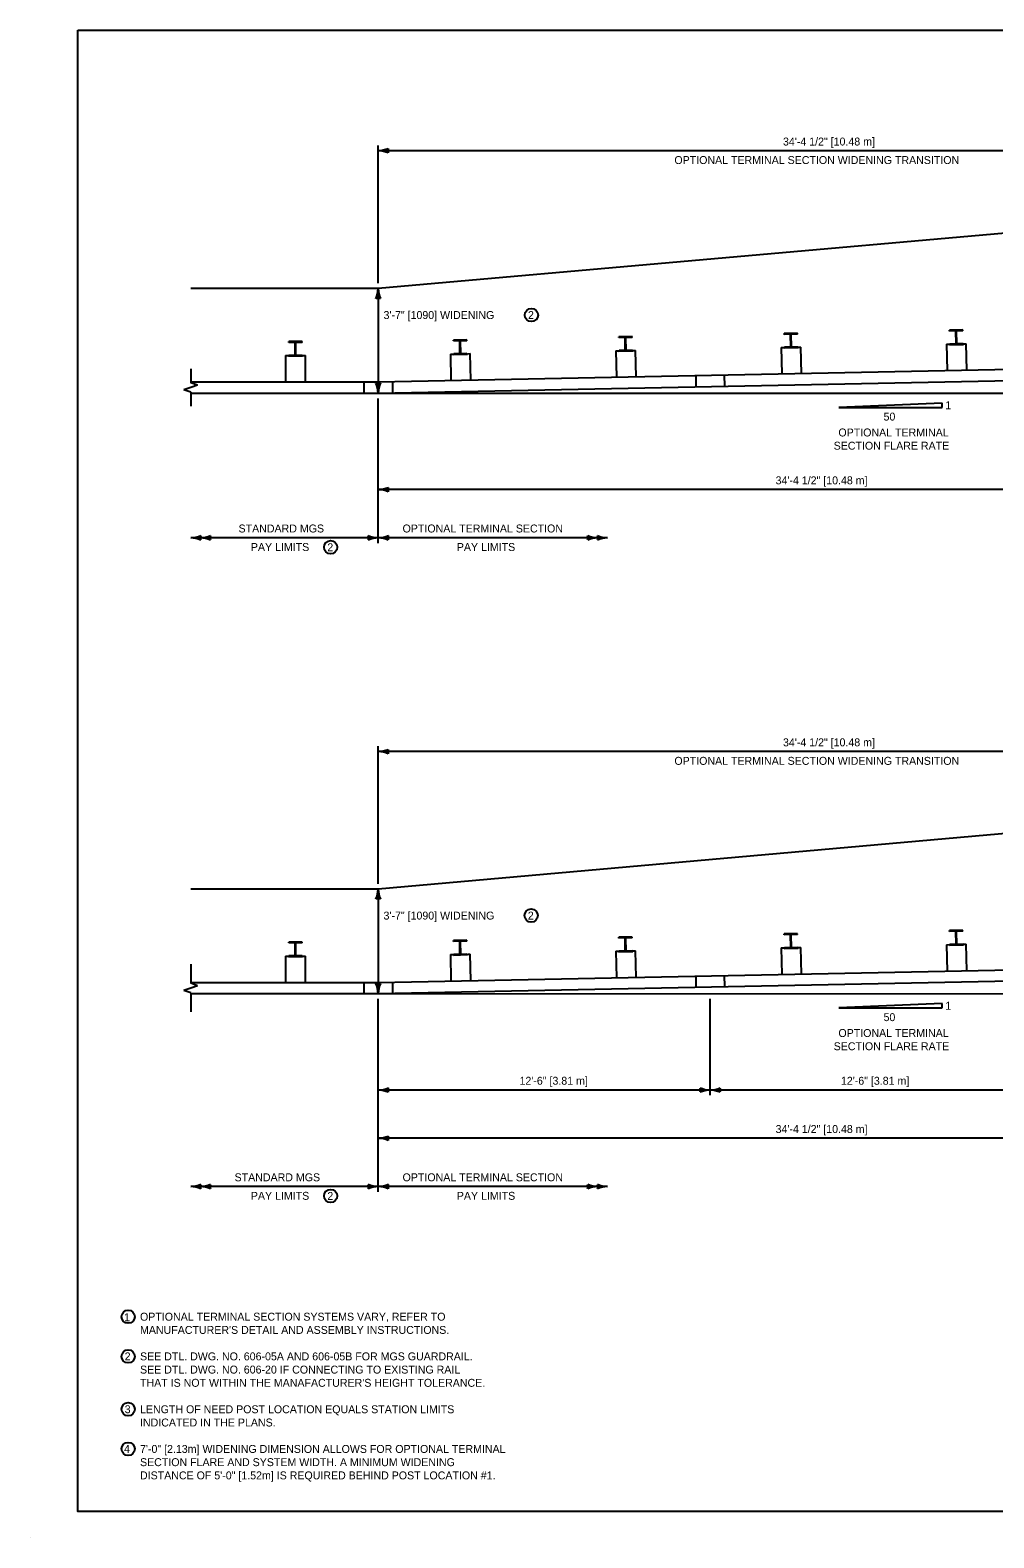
# Model space of a CAD drawing. Extents: x 49991.4 to 50021, y 49987.6 to 50011.4.
# Drawn here: x 49999.02 to 50006.31, y 49987.6 to 49999 of the extents above; entities that cross this region are included whole.
import ezdxf

# ---------------------------------------------------------------- set-up
doc = ezdxf.new("R2010")
doc.units = 0
for name, color, linetype in [('Level 1', 7, 'Continuous'), ('Level 2', 7, 'Continuous'), ('Level 3', 7, 'Continuous'), ('Level 6', 7, 'Continuous')]:
    doc.layers.add(name, color=color, linetype=linetype)

msp = doc.modelspace()

# ---------------------------------------------------------------- linework, layer by layer
at = {"layer": 'Level 1'}
for p, q in [((50008.531, 49997.654), (50001.656, 49997.045)), ((50001.656, 49997.045), (50000.238, 49997.045)), ((50003.575, 49996.683), (50003.475, 49996.681)), ((50003.575, 49996.676), (50003.575, 49996.683)), ((50004.825, 49996.708), (50004.725, 49996.706)), ((50004.725, 49996.699), (50004.725, 49996.706)), ((50004.772, 49996.7), (50004.725, 49996.699)), ((50004.774, 49996.602), (50004.772, 49996.7)), ((50004.825, 49996.701), (50004.778, 49996.7)), ((50004.78, 49996.602), (50004.778, 49996.7)), ((50004.825, 49996.701), (50004.825, 49996.708)), ((50006.075, 49996.733), (50005.975, 49996.731)), ((50005.975, 49996.724), (50005.975, 49996.731)), ((50006.022, 49996.725), (50005.975, 49996.724)), ((50006.024, 49996.627), (50006.022, 49996.725)), ((50006.075, 49996.726), (50006.028, 49996.725)), ((50006.03, 49996.627), (50006.028, 49996.725)), ((50006.075, 49996.726), (50006.075, 49996.733)), ((50001.081, 49996.645), (50000.981, 49996.645)), ((50000.981, 49996.638), (50000.981, 49996.645)), ((50001.028, 49996.638), (50000.981, 49996.638)), ((50001.028, 49996.539), (50001.028, 49996.638)), ((50001.034, 49996.539), (50001.034, 49996.638)), ((50001.081, 49996.638), (50001.034, 49996.638)), ((50001.081, 49996.638), (50001.081, 49996.645)), ((50002.325, 49996.658), (50002.225, 49996.656)), ((50002.225, 49996.649), (50002.225, 49996.656)), ((50002.272, 49996.65), (50002.225, 49996.649)), ((50002.274, 49996.552), (50002.272, 49996.65)), ((50002.325, 49996.651), (50002.278, 49996.65)), ((50002.28, 49996.552), (50002.278, 49996.65)), ((50002.325, 49996.651), (50002.325, 49996.658)), ((50003.452, 49996.575), (50003.456, 49996.375)), ((50003.452, 49996.575), (50003.474, 49996.575)), ((50003.474, 49996.575), (50003.474, 49996.569)), ((50003.58, 49996.571), (50003.474, 49996.569)), ((50003.475, 49996.674), (50003.475, 49996.681)), ((50003.522, 49996.675), (50003.475, 49996.674)), ((50003.524, 49996.577), (50003.477, 49996.576)), ((50003.477, 49996.569), (50003.477, 49996.576)), ((50003.524, 49996.577), (50003.522, 49996.675)), ((50003.575, 49996.676), (50003.528, 49996.675)), ((50003.53, 49996.577), (50003.528, 49996.675)), ((50003.577, 49996.578), (50003.53, 49996.577)), ((50003.577, 49996.571), (50003.577, 49996.578)), ((50003.58, 49996.577), (50003.602, 49996.578)), ((50003.58, 49996.571), (50003.58, 49996.577)), ((50003.606, 49996.378), (50003.602, 49996.578)), ((50004.702, 49996.6), (50004.706, 49996.4)), ((50004.702, 49996.6), (50004.724, 49996.6)), ((50004.724, 49996.6), (50004.724, 49996.594)), ((50004.83, 49996.596), (50004.724, 49996.594)), ((50004.774, 49996.602), (50004.727, 49996.601)), ((50004.727, 49996.594), (50004.727, 49996.601)), ((50004.827, 49996.603), (50004.78, 49996.602)), ((50004.827, 49996.596), (50004.827, 49996.603)), ((50004.83, 49996.602), (50004.852, 49996.603)), ((50004.83, 49996.596), (50004.83, 49996.602)), ((50004.856, 49996.403), (50004.852, 49996.603)), ((50005.952, 49996.625), (50005.956, 49996.425)), ((50005.952, 49996.625), (50005.974, 49996.625)), ((50005.974, 49996.625), (50005.974, 49996.619)), ((50006.08, 49996.621), (50005.974, 49996.619)), ((50006.024, 49996.627), (50005.977, 49996.626)), ((50005.977, 49996.619), (50005.977, 49996.626)), ((50006.077, 49996.628), (50006.03, 49996.627)), ((50006.077, 49996.621), (50006.077, 49996.628)), ((50006.08, 49996.627), (50006.102, 49996.628)), ((50006.08, 49996.621), (50006.08, 49996.627)), ((50006.106, 49996.428), (50006.102, 49996.628)), ((50000.956, 49996.539), (50000.956, 49996.339)), ((50000.956, 49996.539), (50000.978, 49996.539)), ((50000.978, 49996.539), (50000.978, 49996.533)), ((50001.084, 49996.533), (50000.978, 49996.533)), ((50001.028, 49996.539), (50000.981, 49996.539)), ((50000.981, 49996.533), (50000.981, 49996.539)), ((50001.081, 49996.539), (50001.034, 49996.539)), ((50001.081, 49996.533), (50001.081, 49996.539)), ((50001.084, 49996.533), (50001.084, 49996.539)), ((50001.084, 49996.539), (50001.106, 49996.539)), ((50001.106, 49996.339), (50001.106, 49996.539)), ((50001.656, 49996.339), (50009.935, 49996.505)), ((50002.202, 49996.55), (50002.206, 49996.35)), ((50002.202, 49996.55), (50002.224, 49996.55)), ((50002.224, 49996.55), (50002.224, 49996.544)), ((50002.33, 49996.546), (50002.224, 49996.544)), ((50002.274, 49996.552), (50002.227, 49996.551)), ((50002.227, 49996.544), (50002.227, 49996.551)), ((50002.327, 49996.553), (50002.28, 49996.552)), ((50002.327, 49996.546), (50002.327, 49996.553)), ((50002.33, 49996.552), (50002.352, 49996.553)), ((50002.33, 49996.546), (50002.33, 49996.552)), ((50002.356, 49996.353), (50002.352, 49996.553)), ((50001.656, 49996.255), (50009.937, 49996.421)), ((50001.764, 49996.341), (50001.764, 49996.257)), ((50004.056, 49996.387), (50004.057, 49996.303)), ((50004.272, 49996.391), (50004.274, 49996.308)), ((50000.238, 49996.339), (50001.031, 49996.339)), ((50000.238, 49996.255), (50001.656, 49996.255)), ((50000.238, 49996.255), (50015.876, 49996.254)), ((50001.031, 49996.339), (50001.656, 49996.339)), ((50001.548, 49996.339), (50001.548, 49996.255)), ((50008.531, 49993.113), (50001.656, 49992.504)), ((50001.031, 49992.504), (50000.238, 49992.504)), ((50001.656, 49992.504), (50000.238, 49992.504)), ((50003.575, 49992.142), (50003.475, 49992.14)), ((50003.475, 49992.134), (50003.475, 49992.14)), ((50003.522, 49992.135), (50003.475, 49992.134)), ((50003.524, 49992.036), (50003.522, 49992.135)), ((50003.575, 49992.136), (50003.528, 49992.135)), ((50003.53, 49992.036), (50003.528, 49992.135)), ((50003.575, 49992.136), (50003.575, 49992.142)), ((50004.825, 49992.167), (50004.725, 49992.165)), ((50004.725, 49992.159), (50004.725, 49992.165)), ((50004.772, 49992.16), (50004.725, 49992.159)), ((50004.774, 49992.061), (50004.772, 49992.16)), ((50004.825, 49992.161), (50004.778, 49992.16)), ((50004.78, 49992.061), (50004.778, 49992.16)), ((50004.825, 49992.161), (50004.825, 49992.167)), ((50006.075, 49992.192), (50005.975, 49992.19)), ((50005.975, 49992.184), (50005.975, 49992.19)), ((50006.022, 49992.185), (50005.975, 49992.184)), ((50006.024, 49992.086), (50006.022, 49992.185)), ((50006.075, 49992.186), (50006.028, 49992.185)), ((50006.03, 49992.086), (50006.028, 49992.185)), ((50006.075, 49992.186), (50006.075, 49992.192)), ((50001.081, 49992.104), (50000.981, 49992.104)), ((50000.981, 49992.097), (50000.981, 49992.104)), ((50001.028, 49992.097), (50000.981, 49992.097)), ((50001.028, 49991.999), (50001.028, 49992.097)), ((50001.034, 49991.999), (50001.034, 49992.097)), ((50001.081, 49992.097), (50001.034, 49992.097)), ((50001.081, 49992.097), (50001.081, 49992.104)), ((50002.202, 49992.009), (50002.224, 49992.01)), ((50002.202, 49992.009), (50002.206, 49991.809)), ((50002.224, 49992.01), (50002.224, 49992.003)), ((50002.325, 49992.117), (50002.225, 49992.115)), ((50002.225, 49992.109), (50002.225, 49992.115)), ((50002.272, 49992.11), (50002.225, 49992.109)), ((50002.274, 49992.011), (50002.227, 49992.01)), ((50002.227, 49992.004), (50002.227, 49992.01)), ((50002.274, 49992.011), (50002.272, 49992.11)), ((50002.325, 49992.111), (50002.278, 49992.11)), ((50002.28, 49992.011), (50002.278, 49992.11)), ((50002.327, 49992.012), (50002.28, 49992.011)), ((50002.325, 49992.111), (50002.325, 49992.117)), ((50002.327, 49992.006), (50002.327, 49992.012)), ((50002.33, 49992.006), (50002.33, 49992.012)), ((50002.33, 49992.012), (50002.352, 49992.012)), ((50002.356, 49991.812), (50002.352, 49992.012)), ((50003.452, 49992.034), (50003.474, 49992.035)), ((50003.452, 49992.034), (50003.456, 49991.834)), ((50003.474, 49992.035), (50003.474, 49992.028)), ((50003.58, 49992.031), (50003.474, 49992.028)), ((50003.524, 49992.036), (50003.477, 49992.035)), ((50003.477, 49992.029), (50003.477, 49992.035)), ((50003.577, 49992.037), (50003.53, 49992.036)), ((50003.577, 49992.031), (50003.577, 49992.037)), ((50003.58, 49992.031), (50003.58, 49992.037)), ((50003.58, 49992.037), (50003.602, 49992.037)), ((50003.606, 49991.837), (50003.602, 49992.037)), ((50004.702, 49992.059), (50004.724, 49992.06)), ((50004.702, 49992.059), (50004.706, 49991.859)), ((50004.724, 49992.06), (50004.724, 49992.053)), ((50004.83, 49992.056), (50004.724, 49992.053)), ((50004.774, 49992.061), (50004.727, 49992.06)), ((50004.727, 49992.054), (50004.727, 49992.06)), ((50004.827, 49992.062), (50004.78, 49992.061)), ((50004.827, 49992.056), (50004.827, 49992.062)), ((50004.83, 49992.056), (50004.83, 49992.062)), ((50004.83, 49992.062), (50004.852, 49992.062)), ((50004.856, 49991.862), (50004.852, 49992.062)), ((50005.952, 49992.084), (50005.974, 49992.085)), ((50005.952, 49992.084), (50005.956, 49991.884)), ((50005.974, 49992.085), (50005.974, 49992.078)), ((50006.08, 49992.081), (50005.974, 49992.078)), ((50006.024, 49992.086), (50005.977, 49992.085)), ((50005.977, 49992.079), (50005.977, 49992.085)), ((50006.077, 49992.087), (50006.03, 49992.086)), ((50006.077, 49992.081), (50006.077, 49992.087)), ((50006.08, 49992.081), (50006.08, 49992.087)), ((50006.08, 49992.087), (50006.102, 49992.087)), ((50006.106, 49991.887), (50006.102, 49992.087)), ((50000.956, 49991.998), (50000.956, 49991.798)), ((50000.956, 49991.998), (50000.978, 49991.998)), ((50000.978, 49991.998), (50000.978, 49991.992)), ((50001.084, 49991.992), (50000.978, 49991.992)), ((50001.028, 49991.999), (50000.981, 49991.999)), ((50000.981, 49991.992), (50000.981, 49991.999)), ((50001.081, 49991.999), (50001.034, 49991.999)), ((50001.081, 49991.992), (50001.081, 49991.999)), ((50001.084, 49991.992), (50001.084, 49991.998)), ((50001.084, 49991.998), (50001.106, 49991.998)), ((50001.106, 49991.798), (50001.106, 49991.998)), ((50001.656, 49991.798), (50010.202, 49991.969)), ((50002.33, 49992.006), (50002.224, 49992.003)), ((50000.238, 49991.798), (50001.031, 49991.798)), ((50001.031, 49991.798), (50001.656, 49991.798)), ((50001.548, 49991.798), (50001.548, 49991.714)), ((50001.656, 49991.714), (50010.202, 49991.885)), ((50001.764, 49991.8), (50001.764, 49991.717)), ((50004.056, 49991.846), (50004.057, 49991.762)), ((50004.272, 49991.851), (50004.274, 49991.767)), ((50000.238, 49991.714), (50001.656, 49991.714)), ((50000.238, 49991.714), (50015.876, 49991.713)), ((49999.024, 49987.599), (49999.024, 49987.599))]:
    msp.add_line(p, q, dxfattribs=at)
msp.add_lwpolyline([(49999.384, 49998.999), (50016.75, 49998.999), (50016.75, 49987.799), (49999.384, 49987.799)], close=True, dxfattribs=at)
at = {"layer": 'Level 2'}
for p, q in [((50005.92, 49996.178), (50005.138, 49996.147)), ((50005.138, 49996.147), (50005.92, 49996.147)), ((50005.92, 49996.147), (50005.92, 49996.178)), ((50005.92, 49991.638), (50005.138, 49991.606)), ((50005.138, 49991.606), (50005.92, 49991.606)), ((50005.92, 49991.606), (50005.92, 49991.638))]:
    msp.add_line(p, q, dxfattribs=at)
for centre in [(50002.814, 49996.845), (50001.296, 49995.089), (50002.812, 49992.304), (50001.296, 49990.184), (49999.765, 49989.271), (49999.765, 49988.971), (49999.765, 49988.571), (49999.765, 49988.271)]:
    msp.add_circle(centre, 0.05, dxfattribs=at)
at = {"layer": 'Level 3'}
for p, q in [((50001.656, 49997.085), (50001.656, 49998.128)), ((50001.656, 49998.088), (50008.531, 49998.088)), ((50001.656, 49997.045), (50001.656, 49996.255)), ((50001.656, 49995.121), (50001.656, 49996.215)), ((50008.531, 49995.525), (50001.656, 49995.525)), ((50001.656, 49995.161), (50000.238, 49995.161)), ((50003.389, 49995.161), (50001.656, 49995.161)), ((50001.656, 49992.544), (50001.656, 49993.584)), ((50008.531, 49993.544), (50001.656, 49993.544)), ((50001.656, 49992.504), (50001.656, 49991.714)), ((50001.656, 49990.945), (50001.656, 49991.674)), ((50004.165, 49990.945), (50004.165, 49991.674)), ((50001.656, 49990.215), (50001.656, 49991.31)), ((50004.165, 49990.985), (50001.656, 49990.985)), ((50006.665, 49990.985), (50004.165, 49990.985)), ((50008.531, 49990.62), (50001.656, 49990.62)), ((50001.656, 49990.255), (50000.238, 49990.255)), ((50003.389, 49990.255), (50001.656, 49990.255))]:
    msp.add_line(p, q, dxfattribs=at)
for centre, radius, start, end in [((50001.644, 49998.321), 0.233, 272.8273, 292.0772), ((50001.647, 49997.866), 0.222, 67.456, 87.6395), ((50001.784, 49998.088), 0.0548, 162.1388, 197.8612), ((50001.423, 49997.056), 0.233, 337.9228, 357.1727), ((50001.878, 49997.054), 0.222, 182.3605, 202.544), ((50001.656, 49996.916), 0.0548, 72.1388, 107.8612), ((50001.434, 49996.246), 0.222, 2.3605, 22.544), ((50001.656, 49996.383), 0.0548, 252.1388, 287.8612), ((50001.889, 49996.244), 0.233, 157.9228, 177.1727), ((50001.645, 49995.758), 0.233, 272.8273, 292.0772), ((50001.784, 49995.525), 0.0548, 162.1388, 197.8612), ((50001.647, 49995.303), 0.222, 67.456, 87.6395), ((50000.227, 49995.393), 0.233, 272.8273, 292.0772), ((50000.229, 49994.938), 0.222, 67.456, 87.6395), ((50000.366, 49995.161), 0.0548, 162.1388, 197.8612), ((50000.3, 49995.393), 0.233, 272.8273, 292.0772), ((50000.302, 49994.938), 0.222, 67.456, 87.6395), ((50000.44, 49995.161), 0.0548, 162.1388, 197.8612), ((50001.665, 49995.383), 0.222, 247.456, 267.6395), ((50001.528, 49995.161), 0.0548, 342.1388, 17.8612), ((50001.665, 49995.383), 0.222, 247.456, 267.6395), ((50001.528, 49995.161), 0.0548, 342.1388, 17.8612), ((50001.668, 49994.928), 0.233, 92.8273, 112.0772), ((50001.668, 49994.928), 0.233, 92.8273, 112.0772), ((50001.645, 49995.393), 0.233, 272.8273, 292.0772), ((50001.647, 49994.938), 0.222, 67.456, 87.6395), ((50001.784, 49995.161), 0.0548, 162.1388, 197.8612), ((50003.325, 49995.383), 0.222, 247.456, 267.6395), ((50003.187, 49995.161), 0.0548, 342.1388, 17.8612), ((50003.327, 49994.928), 0.233, 92.8273, 112.0772), ((50003.398, 49995.383), 0.222, 247.456, 267.6395), ((50003.261, 49995.161), 0.0548, 342.1388, 17.8612), ((50003.401, 49994.928), 0.233, 92.8273, 112.0772), ((50001.644, 49993.777), 0.233, 272.8273, 292.0772), ((50001.647, 49993.322), 0.222, 67.456, 87.6395), ((50001.784, 49993.544), 0.0548, 162.1388, 197.8612), ((50001.423, 49992.515), 0.233, 337.9228, 357.1727), ((50001.878, 49992.513), 0.222, 182.3605, 202.544), ((50001.656, 49992.376), 0.0548, 72.1388, 107.8612), ((50001.434, 49991.705), 0.222, 2.3605, 22.544), ((50001.656, 49991.843), 0.0548, 252.1388, 287.8612), ((50001.889, 49991.703), 0.233, 157.9228, 177.1727), ((50001.645, 49991.217), 0.233, 272.8273, 292.0772), ((50001.647, 49990.763), 0.222, 67.456, 87.6395), ((50001.784, 49990.985), 0.0548, 162.1388, 197.8612), ((50004.174, 49991.207), 0.222, 247.456, 267.6395), ((50004.037, 49990.985), 0.0548, 342.1388, 17.8612), ((50004.176, 49990.752), 0.233, 92.8273, 112.0772), ((50004.153, 49991.217), 0.233, 272.8273, 292.0772), ((50004.153, 49991.217), 0.233, 272.8273, 292.0772), ((50004.156, 49990.763), 0.222, 67.456, 87.6395), ((50004.156, 49990.763), 0.222, 67.456, 87.6395), ((50004.293, 49990.985), 0.0548, 162.1388, 197.8612), ((50004.293, 49990.985), 0.0548, 162.1388, 197.8612), ((50001.645, 49990.853), 0.233, 272.8273, 292.0772), ((50001.645, 49990.853), 0.233, 272.8273, 292.0772), ((50001.647, 49990.398), 0.222, 67.456, 87.6395), ((50001.647, 49990.398), 0.222, 67.456, 87.6395), ((50001.784, 49990.62), 0.0548, 162.1388, 197.8612), ((50001.784, 49990.62), 0.0548, 162.1388, 197.8612), ((50000.227, 49990.488), 0.233, 272.8273, 292.0772), ((50000.229, 49990.033), 0.222, 67.456, 87.6395), ((50000.366, 49990.255), 0.0548, 162.1388, 197.8612), ((50000.3, 49990.488), 0.233, 272.8273, 292.0772), ((50000.302, 49990.033), 0.222, 67.456, 87.6395), ((50000.44, 49990.255), 0.0548, 162.1388, 197.8612), ((50001.665, 49990.477), 0.222, 247.456, 267.6395), ((50001.528, 49990.255), 0.0548, 342.1388, 17.8612), ((50001.665, 49990.477), 0.222, 247.456, 267.6395), ((50001.528, 49990.255), 0.0548, 342.1388, 17.8612), ((50001.668, 49990.022), 0.233, 92.8273, 112.0772), ((50001.668, 49990.022), 0.233, 92.8273, 112.0772), ((50001.645, 49990.488), 0.233, 272.8273, 292.0772), ((50001.647, 49990.033), 0.222, 67.456, 87.6395), ((50001.784, 49990.255), 0.0548, 162.1388, 197.8612), ((50003.325, 49990.477), 0.222, 247.456, 267.6395), ((50003.187, 49990.255), 0.0548, 342.1388, 17.8612), ((50003.327, 49990.022), 0.233, 92.8273, 112.0772), ((50003.398, 49990.477), 0.222, 247.456, 267.6395), ((50003.261, 49990.255), 0.0548, 342.1388, 17.8612), ((50003.401, 49990.022), 0.233, 92.8273, 112.0772)]:
    msp.add_arc(centre, radius, start, end, dxfattribs=at)
at = {"layer": 'Level 6'}
for p, q in [((50000.238, 49996.439), (50000.238, 49996.333)), ((50000.238, 49996.297), (50000.187, 49996.279)), ((50000.238, 49996.261), (50000.187, 49996.279)), ((50000.289, 49996.315), (50000.238, 49996.333)), ((50000.289, 49996.315), (50000.238, 49996.297)), ((50000.238, 49996.261), (50000.238, 49996.155)), ((50000.238, 49991.937), (50000.238, 49991.792)), ((50000.289, 49991.774), (50000.238, 49991.792)), ((50000.238, 49991.756), (50000.187, 49991.738)), ((50000.238, 49991.721), (50000.187, 49991.738)), ((50000.289, 49991.774), (50000.238, 49991.756)), ((50000.238, 49991.721), (50000.238, 49991.576))]:
    msp.add_line(p, q, dxfattribs=at)

# ---------------------------------------------------------------- texts
at = {"layer": 'Level 2'}
for s, p in [('34\'-4 1/2" [10.48 m]', (50004.716, 49998.127)), ('OPTIONAL TERMINAL SECTION WIDENING TRANSITION', (50003.895, 49997.987)), ('3\'-7" [1090] WIDENING', (50001.696, 49996.815)), ('2', (50002.788, 49996.815)), ('1', (50005.943, 49996.133)), ('50', (50005.476, 49996.047)), ('SECTION FLARE RATE', (50005.099, 49995.827)), ('OPTIONAL TERMINAL ', (50005.135, 49995.927)), ('34\'-4 1/2" [10.48 m]', (50004.66, 49995.565)), ('STANDARD MGS', (50000.6, 49995.201)), ('OPTIONAL TERMINAL SECTION', (50001.84, 49995.201)), ('PAY LIMITS', (50000.693, 49995.061)), ('2', (50001.271, 49995.059)), ('PAY LIMITS', (50002.25, 49995.061)), ('34\'-4 1/2" [10.48 m]', (50004.716, 49993.584)), ('OPTIONAL TERMINAL SECTION WIDENING TRANSITION', (50003.895, 49993.444)), ('3\'-7" [1090] WIDENING', (50001.696, 49992.274)), ('2', (50002.787, 49992.274)), ('50', (50005.476, 49991.506)), ('1', (50005.943, 49991.592)), ('OPTIONAL TERMINAL ', (50005.135, 49991.386)), ('SECTION FLARE RATE', (50005.099, 49991.286)), ('12\'-6" [3.81 m]', (50002.724, 49991.025)), ('12\'-6" [3.81 m]', (50005.154, 49991.025)), ('34\'-4 1/2" [10.48 m]', (50004.66, 49990.66)), ('STANDARD MGS', (50000.57, 49990.295)), ('OPTIONAL TERMINAL SECTION', (50001.84, 49990.295)), ('PAY LIMITS', (50000.693, 49990.155)), ('2', (50001.271, 49990.154)), ('PAY LIMITS', (50002.25, 49990.155)), ('1', (49999.735, 49989.237)), ('OPTIONAL TERMINAL SECTION SYSTEMS VARY, REFER TO', (49999.855, 49989.241)), ("MANUFACTURER'S DETAIL AND ASSEMBLY INSTRUCTIONS.", (49999.855, 49989.141)), ('2', (49999.739, 49988.941)), ('SEE DTL. DWG. NO. 606-05A AND 606-05B FOR MGS GUARDRAIL.', (49999.855, 49988.941)), ('SEE DTL. DWG. NO. 606-20 IF CONNECTING TO EXISTING RAIL', (49999.855, 49988.841)), ("THAT IS NOT WITHIN THE MANAFACTURER'S HEIGHT TOLERANCE.", (49999.855, 49988.741)), ('3', (49999.739, 49988.541)), ('LENGTH OF NEED POST LOCATION EQUALS STATION LIMITS', (49999.855, 49988.541)), ('INDICATED IN THE PLANS.', (49999.855, 49988.441)), ('4', (49999.734, 49988.241)), ('7\'-0" [2.13m] WIDENING DIMENSION ALLOWS FOR OPTIONAL TERMINAL', (49999.855, 49988.241)), ('SECTION FLARE AND SYSTEM WIDTH. A MINIMUM WIDENING', (49999.855, 49988.141)), ('DISTANCE OF 5\'-0" [1.52m] IS REQUIRED BEHIND POST LOCATION #1.', (49999.855, 49988.041))]:
    msp.add_text(s, height=0.06, dxfattribs=at).set_placement(p)

doc.saveas('drawing.dxf')
